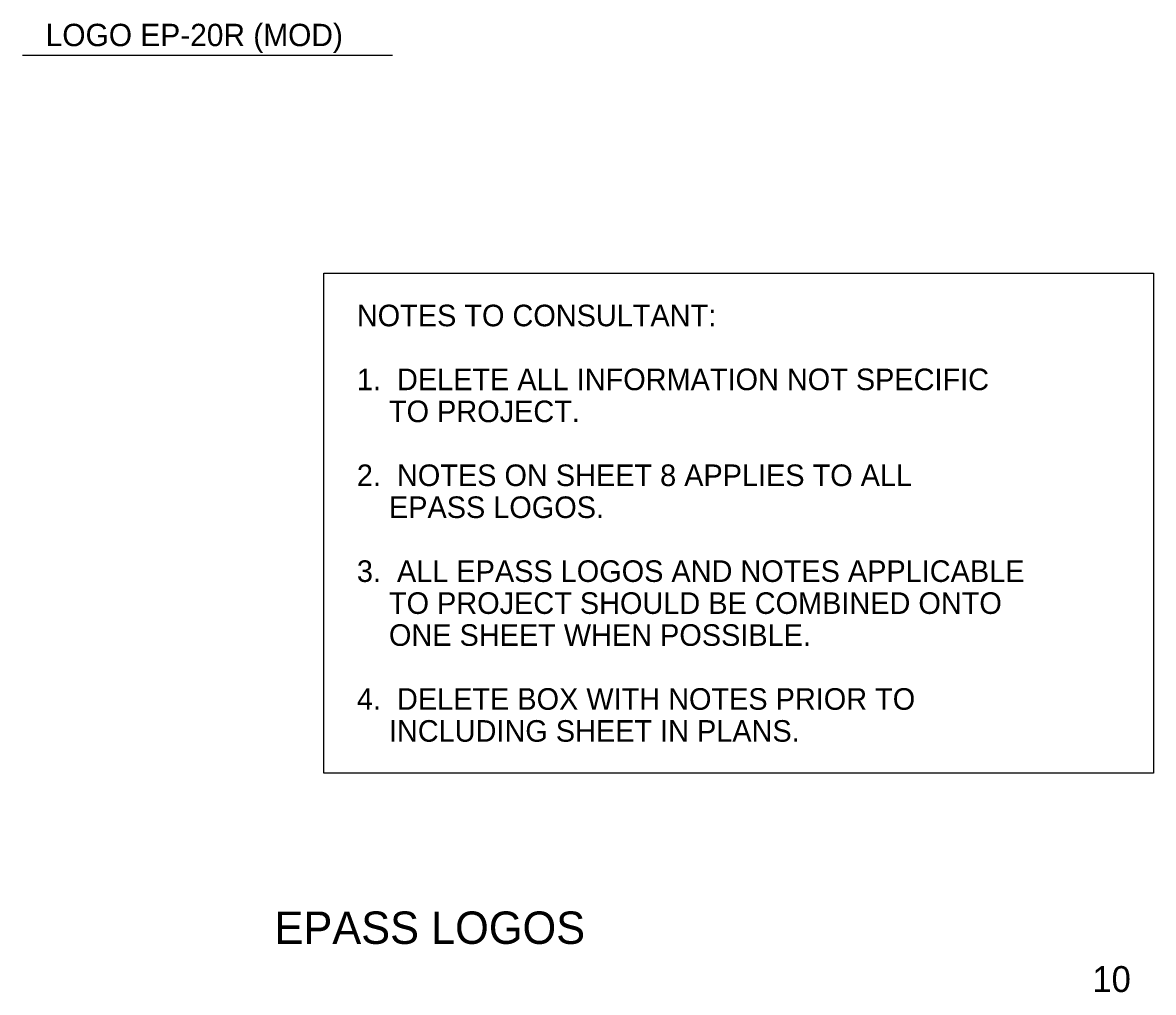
# Model space of a CAD drawing. Extents: x 10268197 to 10268739, y 2141503 to 2142677.
# Drawn here: x 10268695.69 to 10268739.32, y 2142329.12 to 2142366.55 of the extents above; entities that cross this region are included whole.
import ezdxf

# ---------------------------------------------------------------- set-up
doc = ezdxf.new("R2010")
doc.units = 0
for name, color, linetype in [('1', 7, 'Continuous'), ('21', 7, 'Continuous'), ('TextAlert', 7, 'Continuous'), ('TextMisc', 7, 'Continuous'), ('TextShtNo', 7, 'Continuous')]:
    doc.layers.add(name, color=color, linetype=linetype)

msp = doc.modelspace()

# ---------------------------------------------------------------- linework, layer by layer
at = {"layer": '21'}
msp.add_line((10268695.685, 2142365.288), (10268709.96, 2142365.288), dxfattribs=at)
at = {"layer": 'TextAlert'}
msp.add_lwpolyline([(10268707.308, 2142356.875), (10268739.323, 2142356.875), (10268739.323, 2142337.588), (10268707.308, 2142337.588)], close=True, dxfattribs=at)

# ---------------------------------------------------------------- texts
at = {"layer": '1'}
msp.add_text('LOGO EP-20R (MOD)', height=0.8624, dxfattribs=at).set_placement((10268696.576, 2142365.642))
at = {"layer": 'TextAlert'}
for s, p in [('NOTES TO CONSULTANT:', (10268708.584, 2142354.831)), ('1.  DELETE ALL INFORMATION NOT SPECIFIC ', (10268708.584, 2142352.365)), ('    TO PROJECT.', (10268708.584, 2142351.131)), ('2.  NOTES ON SHEET 8 APPLIES TO ALL ', (10268708.584, 2142348.665)), ('    EPASS LOGOS.', (10268708.584, 2142347.431)), ('3.  ALL EPASS LOGOS AND NOTES APPLICABLE', (10268708.584, 2142344.965)), ('    TO PROJECT SHOULD BE COMBINED ONTO', (10268708.584, 2142343.731)), ('    ONE SHEET WHEN POSSIBLE.', (10268708.584, 2142342.498)), ('4.  DELETE BOX WITH NOTES PRIOR TO ', (10268708.584, 2142340.031)), ('    INCLUDING SHEET IN PLANS.', (10268708.584, 2142338.798))]:
    msp.add_text(s, height=0.83333, dxfattribs=at).set_placement(p)
at = {"layer": 'TextMisc'}
msp.add_text('         EPASS LOGOS           ', height=1.25, rotation=360, dxfattribs=at).set_placement((10268701.228, 2142330.996))
at = {"layer": 'TextShtNo'}
msp.add_text('10', height=1, rotation=360, dxfattribs=at).set_placement((10268736.967, 2142329.139))

doc.saveas('drawing.dxf')
